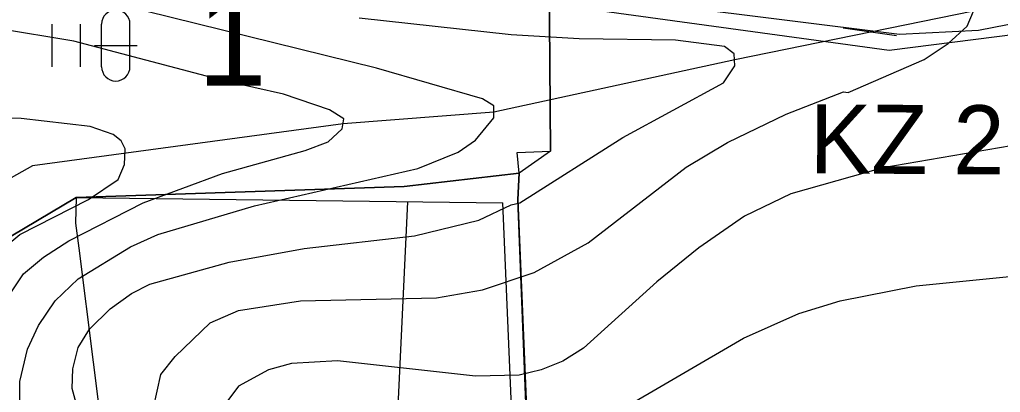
# Model space of a CAD drawing. Extents: x -662500 to -653478, y -1056827 to -1049993.
# Drawn here: x -660935.8 to -660694.1, y -1051848.6 to -1051756.8 of the extents above; entities that cross this region are included whole.
import ezdxf

# ---------------------------------------------------------------- set-up
doc = ezdxf.new("R2010")
doc.units = 0
for name, color, linetype in [('Vrstva 1', 7, 'Continuous'), ('Vrstva 24', 7, 'Continuous'), ('Vrstva 5', 7, 'Continuous'), ('Vrstva 54', 7, 'Continuous'), ('Vrstva 57', 7, 'Continuous'), ('Vrstva 7', 7, 'Continuous')]:
    doc.layers.add(name, color=color, linetype=linetype)

msp = doc.modelspace()

# ---------------------------------------------------------------- linework, layer by layer
at = {"layer": 'Vrstva 1'}
msp.add_line((-660921.87, -1051800.59), (-660816.75, -1051801.98), dxfattribs=at)
for points in [[(-660921.87, -1051800.59), (-660921.98, -1051806.97), (-660921.21, -1051813.09), (-660914.16, -1051869.21), (-660909.2, -1051921.5)], [(-660840.2, -1051801.67), (-660843.43, -1051869.43), (-660841.15, -1051911.77), (-660840.14, -1051952.57), (-660812.31, -1051961.52), (-660811.36, -1051927.44), (-660816.75, -1051801.98)]]:
    msp.add_lwpolyline(points, dxfattribs=at)
at = {"layer": 'Vrstva 24'}
for points in [[(-660511, -1051777), (-660532, -1051761), (-660562.5, -1051747), (-660577, -1051743), (-660585.5, -1051743), (-660623, -1051744.5), (-660699.5, -1051759.5), (-660719, -1051760.5), (-660775, -1051753.5)], [(-660947.48, -1051815.82), (-660921.87, -1051800.59), (-660841.03, -1051797.88), (-660812.66, -1051794.62), (-660812.99, -1051801.1), (-660809.04, -1051897.71)]]:
    msp.add_lwpolyline(points, dxfattribs=at)
at = {"layer": 'Vrstva 5'}
for points in [[(-660805.3, -1051746.13), (-660805.01, -1051789.18), (-660812.66, -1051794.62), (-660841.03, -1051797.88), (-660921.87, -1051800.59), (-660947.48, -1051815.82), (-660972.42, -1051837.01), (-660977.65, -1051834.73), (-660978.09, -1051846.9), (-660986.94, -1051864.68), (-660993.38, -1051881.71), (-661009.02, -1051908.52), (-661023.41, -1051938.54), (-661027.54, -1051947.9), (-661034.54, -1051973.5), (-661041.04, -1051994.91), (-661048.31, -1052024.43)], [(-660972.42, -1051837.01), (-660928.71, -1051891.33), (-660909.06, -1051922.97), (-660840.14, -1051952.57), (-660812.31, -1051961.52), (-660777.56, -1051972.71), (-660777.67, -1051957.47), (-660778.91, -1051942.97), (-660807.46, -1051936.49), (-660808.94, -1051905.69), (-660812.99, -1051801.1), (-660812.66, -1051794.62), (-660813.15, -1051789.53), (-660805.01, -1051789.18), (-660805.3, -1051746.13)], [(-660927.84, -1051757.95), (-660927.84, -1051768.45)], [(-660920.84, -1051757.95), (-660920.84, -1051768.45)], [(-660915.59, -1051768.45), (-660915.59, -1051757.95)], [(-660908.59, -1051768.45), (-660908.59, -1051757.95)], [(-660917.34, -1051763.2), (-660906.84, -1051763.2)]]:
    msp.add_lwpolyline(points, dxfattribs=at)
msp.add_lwpolyline([(-660972.42, -1051837.01), (-660947.48, -1051815.82), (-660921.87, -1051800.59), (-660841.03, -1051797.88), (-660812.66, -1051794.62), (-660812.99, -1051801.1), (-660808.94, -1051905.69), (-660807.46, -1051936.49), (-660793.87, -1051937.97), (-660778.91, -1051942.97), (-660777.67, -1051957.47), (-660777.56, -1051972.71), (-660840.14, -1051952.57), (-660909.06, -1051922.97), (-660928.71, -1051891.33)], close=True, dxfattribs=at)
for centre, start, end in [((-660912.09, -1051757.95), 0, 180), ((-660912.09, -1051768.45), 180, 0)]:
    msp.add_arc(centre, 3.5, start, end, dxfattribs=at)
at = {"layer": 'Vrstva 54'}
msp.add_lwpolyline([(-661061.27, -1051999.59), (-661050.24, -1051980.46), (-661044.92, -1051955.41), (-661013, -1051874.07), (-660972.1, -1051779.61), (-660941.44, -1051708.81), (-660929, -1051706.7), (-660806.12, -1051752.81), (-660721.57, -1051764.39), (-660637.41, -1051753.69), (-660533.68, -1051733.93), (-660461.07, -1051720.1)], dxfattribs=at)
at = {"layer": 'Vrstva 57'}
msp.add_line((-660732.9, -1051758.83), (-660719.74, -1051760.71), dxfattribs=at)
msp.add_lwpolyline([(-660700.73, -1051754.78), (-660759.57, -1051766.74), (-660818.96, -1051779.66), (-660856.09, -1051782.51), (-660932.64, -1051792.79), (-660951.67, -1051803.48), (-660977.9, -1051833.27), (-660993.8, -1051863.48), (-661010.03, -1051906.05), (-661027.36, -1051942.94), (-661034.91, -1051959.02), (-661044.14, -1051987.24), (-661052.39, -1052027.89)], dxfattribs=at)
at = {"layer": 'Vrstva 7'}
for p, q in [((-660847.83, -1051768.81), (-660904.8, -1051754.78)), ((-660702.29, -1051758.47), (-660700.73, -1051754.78)), ((-660814.67, -1051760.59), (-660852.09, -1051756.48)), ((-660922.38, -1051762.15), (-660946.19, -1051758.19)), ((-660706.97, -1051762.72), (-660702.29, -1051758.47)), ((-660885.39, -1051771.93), (-660922.38, -1051762.15)), ((-660797.95, -1051761.59), (-660814.67, -1051760.59)), ((-660774.14, -1051761.87), (-660797.95, -1051761.59)), ((-660762.09, -1051763.43), (-660774.14, -1051761.87)), ((-660712.92, -1051766.69), (-660706.97, -1051762.72)), ((-660759.69, -1051765.27), (-660762.09, -1051763.43)), ((-660759.54, -1051768.25), (-660759.69, -1051765.27)), ((-660731.63, -1051774.77), (-660712.92, -1051766.69)), ((-660821.76, -1051776.32), (-660847.83, -1051768.81)), ((-660762.38, -1051772.36), (-660759.54, -1051768.25)), ((-660870.79, -1051775.19), (-660885.39, -1051771.93)), ((-660787.18, -1051785.82), (-660762.38, -1051772.36)), ((-660746.93, -1051780.15), (-660732.76, -1051774.62)), ((-660732.76, -1051774.62), (-660731.63, -1051774.77)), ((-660859.45, -1051779.02), (-660870.79, -1051775.19)), ((-660818.92, -1051778.02), (-660821.76, -1051776.32)), ((-660855.91, -1051781.28), (-660859.45, -1051779.02)), ((-660818.92, -1051781), (-660818.92, -1051778.02)), ((-660935.42, -1051781.14), (-660947.89, -1051781)), ((-660918.41, -1051783.13), (-660935.42, -1051781.14)), ((-660856.34, -1051783.69), (-660855.91, -1051781.28)), ((-660823.46, -1051786.53), (-660818.92, -1051781)), ((-660761.39, -1051787.09), (-660746.93, -1051780.15)), ((-660912.74, -1051785.11), (-660918.41, -1051783.13)), ((-660859.74, -1051786.95), (-660856.34, -1051783.69)), ((-660672.11, -1051784.54), (-660723.12, -1051793.33)), ((-660910.76, -1051786.67), (-660912.74, -1051785.11)), ((-660909.76, -1051788.65), (-660910.76, -1051786.67)), ((-660865.41, -1051789.08), (-660859.74, -1051786.95)), ((-660827.71, -1051789.5), (-660823.46, -1051786.53)), ((-660812.55, -1051801.98), (-660787.18, -1051785.82)), ((-660771.59, -1051793.19), (-660761.39, -1051787.09)), ((-660909.91, -1051792.48), (-660909.76, -1051788.65)), ((-660885.81, -1051794.75), (-660865.41, -1051789.08)), ((-660837.63, -1051793.47), (-660827.71, -1051789.5)), ((-660911.46, -1051796.16), (-660909.91, -1051792.48)), ((-660877.88, -1051802.68), (-660837.63, -1051793.47)), ((-660795.68, -1051811.75), (-660771.59, -1051793.19)), ((-660723.12, -1051793.33), (-660745.8, -1051799.71)), ((-660918.83, -1051801.12), (-660911.46, -1051796.16)), ((-660905.37, -1051801.98), (-660885.81, -1051794.75)), ((-660935.7, -1051809.77), (-660918.83, -1051801.12)), ((-660745.8, -1051799.71), (-660757.14, -1051805.23)), ((-660923.65, -1051811.33), (-660905.37, -1051801.98)), ((-660901.69, -1051809.77), (-660877.88, -1051802.68)), ((-660822.61, -1051806.23), (-660814.67, -1051802.4)), ((-660814.67, -1051802.4), (-660812.55, -1051801.98)), ((-660838.48, -1051810.05), (-660822.61, -1051806.23)), ((-660757.14, -1051805.23), (-660768.47, -1051813.03)), ((-660945.48, -1051817.85), (-660935.7, -1051809.77)), ((-660908.49, -1051812.75), (-660901.69, -1051809.77)), ((-660865.69, -1051813.17), (-660838.48, -1051810.05)), ((-660929.89, -1051815.3), (-660923.65, -1051811.33)), ((-660921.39, -1051820.68), (-660908.49, -1051812.75)), ((-660884.11, -1051816.57), (-660865.69, -1051813.17)), ((-660809, -1051819.12), (-660795.68, -1051811.75)), ((-660768.47, -1051813.03), (-660778.82, -1051821.39)), ((-660934.85, -1051819.41), (-660929.89, -1051815.3)), ((-660714.9, -1051822.38), (-660647.73, -1051815.72)), ((-660903.67, -1051821.96), (-660884.11, -1051816.57)), ((-660942.64, -1051831.03), (-660934.85, -1051819.41)), ((-660927.05, -1051826.07), (-660921.39, -1051820.68)), ((-660821.76, -1051823.37), (-660809, -1051819.12)), ((-660908.2, -1051824.23), (-660903.67, -1051821.96)), ((-660833.1, -1051825.36), (-660821.76, -1051823.37)), ((-660778.82, -1051821.39), (-660796.82, -1051837.69)), ((-660733.61, -1051826.07), (-660714.9, -1051822.38)), ((-660913.45, -1051828.05), (-660908.2, -1051824.23)), ((-660866.54, -1051826.07), (-660833.1, -1051825.36)), ((-660931.16, -1051832.16), (-660927.05, -1051826.07)), ((-660918.55, -1051833.01), (-660913.45, -1051828.05)), ((-660881.85, -1051828.48), (-660866.54, -1051826.07)), ((-660743.81, -1051829.19), (-660733.61, -1051826.07)), ((-660888.79, -1051831.45), (-660881.85, -1051828.48)), ((-660757.42, -1051835.28), (-660743.81, -1051829.19)), ((-660933.86, -1051837.97), (-660931.16, -1051832.16)), ((-660921.39, -1051837.55), (-660918.55, -1051833.01)), ((-660897.44, -1051839.81), (-660888.79, -1051831.45)), ((-660789.16, -1051853.7), (-660757.42, -1051835.28)), ((-660922.66, -1051842.79), (-660921.39, -1051837.55)), ((-660796.82, -1051837.69), (-660801.92, -1051840.95)), ((-660935.7, -1051845.91), (-660933.86, -1051837.97)), ((-660900.98, -1051844.21), (-660897.44, -1051839.81)), ((-660868.81, -1051841.51), (-660874.48, -1051843.07)), ((-660857.47, -1051840.81), (-660868.81, -1051841.51)), ((-660823.46, -1051844.63), (-660857.47, -1051840.81)), ((-660801.92, -1051840.95), (-660807.3, -1051843.07)), ((-660922.8, -1051847.61), (-660922.66, -1051842.79)), ((-660902.82, -1051852.43), (-660900.98, -1051844.21)), ((-660874.48, -1051843.07), (-660881.85, -1051847.04)), ((-660812.69, -1051844.35), (-660823.46, -1051844.63)), ((-660807.3, -1051843.07), (-660812.69, -1051844.35)), ((-660935.7, -1051851.58), (-660935.7, -1051845.91)), ((-660881.85, -1051847.04), (-660887.94, -1051855.26)), ((-660921.81, -1051851.29), (-660922.8, -1051847.61))]:
    msp.add_line(p, q, dxfattribs=at)

# ---------------------------------------------------------------- texts
at = {"layer": 'Vrstva 54'}
msp.add_text('KZ 2', height=17, rotation=359.642, dxfattribs=at).set_placement((-660741.17, -1051794.67))
at = {"layer": 'Vrstva 57'}
msp.add_text('1', height=23, dxfattribs=at).set_placement((-660891.96, -1051773.08))

doc.saveas('drawing.dxf')
